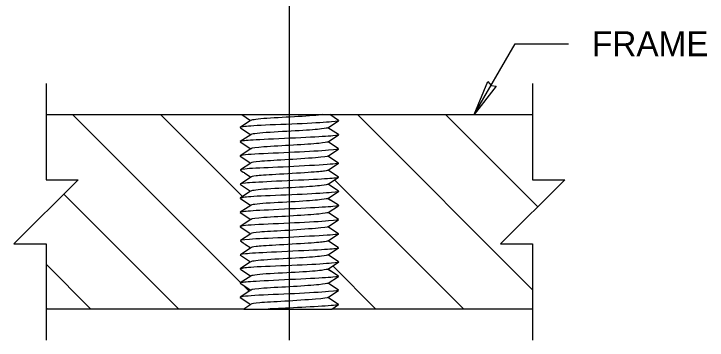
# Model space of a CAD drawing. Extents: x 99862 to 103151, y 100000 to 102076.
# Drawn here: x 101530 to 101975.2, y 101405.7 to 101615.5 of the extents above; entities that cross this region are included whole.
import ezdxf

# ---------------------------------------------------------------- set-up
doc = ezdxf.new("R2010")
doc.units = 0
for name, color, linetype in [('Level 1', 7, 'Continuous'), ('Level 14', 7, 'Continuous'), ('Level 15', 7, 'Continuous'), ('Level 17', 7, 'Continuous'), ('Level 2', 7, 'Continuous'), ('Level 20', 7, 'Continuous')]:
    doc.layers.add(name, color=color, linetype=linetype)

msp = doc.modelspace()

# ---------------------------------------------------------------- linework, layer by layer
at = {"layer": 'Level 1'}
for p, q in [((101682.03, 101546.9), (101675.35, 101542.46)), ((101676.34, 101550.72), (101682.03, 101546.9)), ((101738.45, 101546.95), (101732.84, 101550.72)), ((101731.72, 101542.33), (101738.45, 101546.81)), ((101675.51, 101542.22), (101682.06, 101537.83)), ((101738.38, 101537.86), (101731.72, 101542.33)), ((101682.06, 101537.83), (101675.38, 101533.42)), ((101731.78, 101533.24), (101738.45, 101537.64)), ((101675.38, 101533.21), (101682.08, 101528.71)), ((101738.45, 101528.77), (101731.78, 101533.24)), ((101682.08, 101528.71), (101675.38, 101524.26)), ((101731.72, 101524.12), (101738.45, 101528.62)), ((101675.38, 101524.04), (101682.06, 101519.56)), ((101738.45, 101519.61), (101731.72, 101524.12)), ((101682.06, 101519.56), (101675.44, 101515.17)), ((101731.83, 101515.02), (101738.45, 101519.46)), ((101738.45, 101510.59), (101731.83, 101515.02)), ((101682.09, 101510.53), (101675.44, 101506.08)), ((101731.78, 101505.97), (101738.45, 101510.44)), ((101675.44, 101505.86), (101682.03, 101501.45)), ((101738.45, 101501.5), (101731.78, 101505.97)), ((101682.03, 101501.45), (101675.35, 101497.01)), ((101731.72, 101496.88), (101738.45, 101501.35)), ((101675.51, 101496.77), (101682.06, 101492.38)), ((101738.38, 101492.41), (101731.72, 101496.88)), ((101682.06, 101492.38), (101675.38, 101487.97)), ((101731.78, 101487.79), (101738.45, 101492.19)), ((101675.38, 101487.75), (101682.08, 101483.26)), ((101738.45, 101483.32), (101731.78, 101487.79)), ((101682.08, 101483.26), (101675.38, 101478.81)), ((101731.72, 101478.66), (101738.45, 101483.17)), ((101675.38, 101478.59), (101682.06, 101474.11)), ((101738.45, 101474.15), (101731.72, 101478.66)), ((101682.06, 101474.11), (101675.44, 101469.72)), ((101731.83, 101469.57), (101738.45, 101474.01)), ((101738.45, 101465.13), (101731.83, 101469.57)), ((101682.09, 101465.08), (101675.44, 101460.62)), ((101731.78, 101460.52), (101738.45, 101464.99)), ((101675.44, 101460.41), (101682.03, 101455.99)), ((101738.45, 101456.04), (101731.78, 101460.52)), ((101682.03, 101455.99), (101675.35, 101451.55)), ((101731.72, 101451.42), (101738.45, 101455.9)), ((101675.51, 101451.32), (101682.06, 101446.92)), ((101738.38, 101446.95), (101731.72, 101451.42)), ((101682.06, 101446.92), (101675.38, 101442.52)), ((101731.78, 101442.33), (101738.45, 101446.73)), ((101675.38, 101442.3), (101682.08, 101437.8)), ((101738.45, 101437.86), (101731.78, 101442.33)), ((101682.08, 101437.8), (101675.38, 101433.35)), ((101731.72, 101433.21), (101738.45, 101437.72)), ((101675.38, 101433.13), (101682.06, 101428.66)), ((101738.45, 101428.7), (101731.72, 101433.21)), ((101682.06, 101428.66), (101677.63, 101425.72)), ((101734.22, 101425.72), (101738.45, 101428.55))]:
    msp.add_line(p, q, dxfattribs=at)
for points in [[(101675.44, 101514.95), (101677.15, 101513.79), (101677.78, 101513.42)], [(101678.04, 101513.21), (101682.09, 101510.53)], [(101675.44, 101469.5), (101677.15, 101468.33), (101677.78, 101467.97)], [(101678.04, 101467.75), (101682.09, 101465.08)]]:
    msp.add_lwpolyline(points, dxfattribs=at)
at = {"layer": 'Level 14'}
for p, q in [((101676.34, 101550.72), (101732.84, 101550.72)), ((101677.63, 101425.72), (101734.22, 101425.72))]:
    msp.add_line(p, q, dxfattribs=at)
for points in [[(101731.81, 101542.28), (101733.32, 101541.28)], [(101731.81, 101496.82), (101733.32, 101495.82)], [(101731.81, 101451.37), (101733.32, 101450.37)]]:
    msp.add_lwpolyline(points, dxfattribs=at)
for points in [[(101738.45, 101546.95), (101738.7, 101546.81), (101736.8, 101546.22), (101717.32, 101544.84), (101685, 101543.82), (101674.87, 101542.73), (101675.25, 101542.22), (101675.32, 101542.22)], [(101728.43, 101550.72), (101725.27, 101550.31), (101713.57, 101549.36), (101690.63, 101548.41), (101682.85, 101547.39), (101682.21, 101547.02)], [(101731.55, 101542.22), (101731.43, 101542.15), (101729.34, 101541.57), (101715.11, 101540.33), (101689.8, 101539.24), (101682.09, 101538.22), (101682.09, 101537.79)], [(101738.45, 101537.86), (101738.7, 101537.72), (101737.37, 101537.13), (101719.98, 101536.12), (101687.21, 101534.59), (101675.19, 101533.79), (101675.25, 101533.28), (101675.38, 101533.21)], [(101731.55, 101533.13), (101731.24, 101532.92), (101727.88, 101532.33), (101710.24, 101531.02), (101688.35, 101530.01), (101682.78, 101529.21), (101682.28, 101528.84)], [(101738.45, 101528.77), (101738.83, 101528.55), (101735.22, 101527.9), (101711.12, 101526.44), (101681.45, 101525.35), (101674.75, 101524.48), (101675.38, 101524.04)], [(101731.68, 101524.12), (101731.74, 101523.75), (101726.05, 101523.1), (101702.9, 101521.5), (101685.82, 101520.7), (101682.66, 101519.97), (101682.34, 101519.75)], [(101738.45, 101519.61), (101739.02, 101519.24), (101732, 101518.59), (101701.76, 101516.92), (101678.23, 101516.04), (101675, 101515.24), (101675.44, 101514.95)], [(101731.62, 101514.95), (101731.62, 101514.95), (101730.92, 101514.52), (101721.68, 101513.57), (101695.88, 101512.12), (101683.86, 101511.32), (101682.4, 101510.73), (101682.28, 101510.66)], [(101738.45, 101510.59), (101738.57, 101510.52), (101738.45, 101510.01), (101725.73, 101509.06), (101692.78, 101507.61), (101676.14, 101506.66), (101675.19, 101506.01), (101675.44, 101505.86)], [(101731.55, 101505.86), (101731.43, 101505.79), (101729.34, 101505.21), (101715.11, 101503.97), (101690.63, 101502.95), (101682.85, 101501.93), (101682.21, 101501.57)], [(101738.45, 101501.5), (101738.7, 101501.35), (101736.8, 101500.77), (101717.32, 101499.39), (101685, 101498.37), (101674.87, 101497.28), (101675.25, 101496.77), (101675.32, 101496.77)], [(101731.55, 101496.77), (101731.43, 101496.7), (101729.34, 101496.12), (101715.11, 101494.88), (101689.8, 101493.79), (101682.09, 101492.77), (101682.09, 101492.33)], [(101738.45, 101492.41), (101738.7, 101492.26), (101737.37, 101491.68), (101719.98, 101490.66), (101687.21, 101489.13), (101675.19, 101488.33), (101675.25, 101487.82), (101675.38, 101487.75)], [(101731.55, 101487.68), (101731.24, 101487.46), (101727.88, 101486.88), (101710.24, 101485.57), (101688.35, 101484.55), (101682.78, 101483.75), (101682.28, 101483.39)], [(101738.45, 101483.32), (101738.83, 101483.1), (101735.22, 101482.44), (101711.12, 101480.99), (101681.45, 101479.9), (101674.75, 101479.02), (101675.38, 101478.59)], [(101731.68, 101478.66), (101731.74, 101478.3), (101726.05, 101477.64), (101702.9, 101476.04), (101685.82, 101475.24), (101682.66, 101474.52), (101682.34, 101474.3)], [(101738.45, 101474.15), (101739.02, 101473.79), (101732, 101473.13), (101701.76, 101471.46), (101678.23, 101470.59), (101675, 101469.79), (101675.44, 101469.5)], [(101731.62, 101469.5), (101731.62, 101469.5), (101730.92, 101469.06), (101721.68, 101468.12), (101695.88, 101466.66), (101683.86, 101465.86), (101682.4, 101465.28), (101682.28, 101465.21)], [(101738.45, 101465.13), (101738.57, 101465.06), (101738.45, 101464.55), (101725.73, 101463.61), (101692.78, 101462.15), (101676.14, 101461.21), (101675.19, 101460.55), (101675.44, 101460.41)], [(101731.55, 101460.41), (101731.43, 101460.33), (101729.34, 101459.75), (101715.11, 101458.52), (101690.63, 101457.5), (101682.85, 101456.48), (101682.21, 101456.12)], [(101738.45, 101456.04), (101738.7, 101455.9), (101736.8, 101455.32), (101717.32, 101453.93), (101685, 101452.92), (101674.87, 101451.82), (101675.25, 101451.32), (101675.32, 101451.32)], [(101731.55, 101451.32), (101731.43, 101451.24), (101729.34, 101450.66), (101715.11, 101449.42), (101689.8, 101448.33), (101682.09, 101447.32), (101682.09, 101446.88)], [(101738.45, 101446.95), (101738.7, 101446.81), (101737.37, 101446.22), (101719.98, 101445.21), (101687.21, 101443.68), (101675.19, 101442.88), (101675.25, 101442.37), (101675.38, 101442.3)], [(101731.55, 101442.22), (101731.24, 101442.01), (101727.88, 101441.42), (101710.24, 101440.12), (101688.35, 101439.1), (101682.78, 101438.3), (101682.28, 101437.93)], [(101738.45, 101437.86), (101738.83, 101437.64), (101735.22, 101436.99), (101711.12, 101435.53), (101681.45, 101434.44), (101674.75, 101433.57), (101675.38, 101433.13)], [(101731.68, 101433.21), (101731.74, 101432.84), (101726.05, 101432.19), (101702.9, 101430.59), (101685.82, 101429.79), (101682.66, 101429.06), (101682.34, 101428.84)], [(101738.45, 101428.7), (101739.02, 101428.33), (101732, 101427.68), (101708.78, 101426.39), (101696.25, 101425.85), (101693.39, 101425.72)]]:
    msp.add_open_spline(points, degree=3, dxfattribs=at)
at = {"layer": 'Level 15'}
for p, q in [((101706.88, 102060.7), (101706.88, 101405.72)), ((101825.65, 101550.72), (101851.97, 101596.31)), ((101851.97, 101596.31), (101886.27, 101596.31))]:
    msp.add_line(p, q, dxfattribs=at)
for points in [[(101550.62, 101570.72), (101550.62, 101508.86), (101571.26, 101508.86), (101529.97, 101467.57), (101550.62, 101467.57), (101550.62, 101405.72)], [(101863.15, 101570.72), (101863.15, 101508.86), (101883.8, 101508.86), (101842.5, 101467.57), (101863.15, 101467.57), (101863.15, 101405.72)]]:
    msp.add_lwpolyline(points, dxfattribs=at)
msp.add_lwpolyline([(101825.65, 101550.72), (101834.48, 101571.98), (101836.53, 101569.57), (101839.65, 101568.99)], close=True, dxfattribs=at)
at = {"layer": 'Level 17'}
for p, q in [((101567.57, 101550.72), (101675.66, 101442.63)), ((101624.14, 101550.72), (101676.95, 101497.91)), ((101750.6, 101550.72), (101863.15, 101438.17)), ((101807.17, 101550.72), (101866.53, 101491.35)), ((101735.97, 101508.78), (101819.03, 101425.72)), ((101562.07, 101499.65), (101636, 101425.72)), ((101679.9, 101466.67), (101681.74, 101464.83)), ((101550.62, 101454.53), (101579.43, 101425.72)), ((101734.78, 101453.4), (101762.46, 101425.72)), ((101677.03, 101441.25), (101681.14, 101437.14)), ((101550.62, 101426.25), (101551.15, 101425.72))]:
    msp.add_line(p, q, dxfattribs=at)
at = {"layer": 'Level 2'}
for p, q in [((101550.62, 101550.72), (101676.34, 101550.72)), ((101732.84, 101550.72), (101863.15, 101550.72)), ((101677.63, 101425.72), (101550.62, 101425.72)), ((101863.15, 101425.72), (101734.22, 101425.72))]:
    msp.add_line(p, q, dxfattribs=at)

# ---------------------------------------------------------------- texts
at = {"layer": 'Level 20'}
msp.add_text('FRAME', height=16, rotation=360, dxfattribs=at).set_placement((101901.27, 101588.31))

doc.saveas('drawing.dxf')
